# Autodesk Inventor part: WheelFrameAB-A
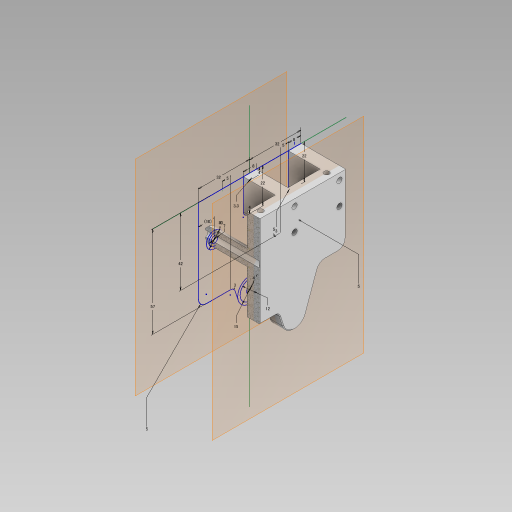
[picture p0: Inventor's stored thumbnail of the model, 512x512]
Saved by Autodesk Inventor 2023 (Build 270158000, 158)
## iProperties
Created: 2024-05
Part Number: WheelFrameAB-A
Material: 一般
Document SubType Name: Modeling
Designer: kumagai
Density: 1 g/cm^3
Appearance: 既定
Author: kumagai
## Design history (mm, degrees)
derived "WheelUnitCoreSketch.ipt"
  sketch "BaseSketch"
    geometry: L1 (0, -60.2)-(0, 60.2) reference; L2 (-60.2, 0)-(60.2, 0) reference; L3 (19, 34.059)-(19, -34.059) reference; L4 (28, 27.148)-(28, -27.148) reference; L5 (-19, 34.059)-(-19, -34.059) reference; L6 (-28, 27.148)-(-28, -27.148) reference; C1 r 43 at (0, 0) reference; 7 further points
    constraints: 1 other
  sketch "Side"
    geometry: L1 (-85.136, 0)-(85.136, 0) reference; L2 (0, 60.2)-(0, -60.2) reference; L3 (0, 22)-(-24.895, 22) reference; C1 r 10 at (-24.895, 22) reference; C2 r 34 at (-63, 0) reference; C3 r 40 at (-63, 0) reference; C4 r 2 at (-24.895, 22) reference; C5 r 17 at (-24.895, 22) reference; 2 further points
  sketch "Front"
    geometry: L1 (0, -97)-(0, -29) reference; L2 (0, -103)-(0, -23) reference; L3 (-60.2, 0)-(60.2, 0) reference; L4 (-28, 0)-(-20, 0) reference; L5 (-20, 0)-(-20, -79.404) reference; L6 (-20, -79.404)-(-28, -79.404) reference; L7 (-28, -79.404)-(-28, 0) reference; L8 (20, 0)-(28, 0) reference; L9 (28, 0)-(28, -72) reference; L10 (28, -72)-(20, -72) reference; L11 (20, -72)-(20, 0) reference; L12 (0, 0)-(0, 13.248) reference; L13 (-6, -23)-(6, -23) reference; L14 (6, -23)-(6, -103) reference; L15 (6, -103)-(-6, -103) reference; L16 (-6, -103)-(-6, -23) reference; L17 (-6.5, -29)-(-10.5, -29) reference; L18 (-10.5, -29)-(-10.5, -97) reference; L19 (-10.5, -97)-(-6.5, -97) reference; L20 (-6.5, -97)-(-6.5, -29) reference; L21 (-10.5, -34.895)-(-6.5, -34.895) reference; L22 (-6.5, -34.895)-(-6.5, -14.895) reference; L23 (-6.5, -14.895)-(-10.5, -14.895) reference; L24 (-10.5, -14.895)-(-10.5, -34.895) reference; L25 (-15.456, -24.895)-(-4.042, -24.895) reference; L26 (-18, -7.895)-(-18, -41.895) reference; L27 (-18, -7.895)-(-10.5, -14.895) reference; L28 (-10.5, -34.895)-(-18, -41.895) reference; 4 further points
sketch "スケッチ4"
  geometry: L1 (0, 60.2)-(0, -60.2) reference; L2 (-42, -19)-(-42, -27); L3 (-45.316, -14.292)-(-65.526, -7.062); L4 (-57, 27)-(-57, 12); L5 (-59.079, 9.145)-(-65.302, 7.138); L6 (0, -32)-(-37, -32); L7 (0, 32)-(-52, 32); L8 (0, 32)-(0, -32); L9 (0, 4)-(-19, 4); L10 (-22, 1)-(-22, -1); L11 (-19, -4)-(0, -4); L12 (0, -24)-(-19, -24); L13 (-22, -27)-(-22, -32); L14 (2.769, -28)-(1.321, -28); C1 r 2 at (-63, 0); C2 r 2 at (-24.895, 22); C3 r 6 at (-63, 0); C4 r 1.65 at (-4, 0); C5 r 1.65 at (-18, 0); C6 r 1.65 at (-4, -28); C7 r 1.65 at (-18, -28); C8 r 3.5 at (-24.895, 22); C9 r 5 at (-24.895, 22); A1 r 7.5 centre (-63, 0) between (-65.526, -7.062) and (-65.302, 7.138); A2 r 5 centre (-47, -19) between (-42, -19) and (-45.316, -14.292); A3 r 3 centre (-60, 12) between (-59.079, 9.145) and (-57, 12); A4 r 5 centre (-37, -27) between (-42, -27) and (-37, -32); A5 r 5 centre (-52, 27) between (-52, 32) and (-57, 27); A6 r 3 centre (-19, -27) between (-19, -24) and (-22, -27); A7 r 3 centre (-19, -1) between (-22, -1) and (-19, -4); A8 r 3 centre (-19, 1) between (-19, 4) and (-22, 1); A9 r 3 centre (-19, -29) between (-22, -29) and (-19, -32); 16 further points
  constraints: 26 end point, 18 centre point, 18 point on circle, 18 tangent, 16 point on line, 6 coincident, 6 equal radius, 2 vertical alignment, 1 parallel, 4 other
  dimensions: "d1" = 4 diameter of C1; "d2" = 4 diameter of C2; "d3" = 42 distance between parallel lines of L2 L1; "d4" = 5 vertical distance of L2.start point (0, -24); "d5" = 15 diameter of A1; "d6" = 5 radius of A2; "d7" = 57 distance between parallel lines of L4 L1; "d8" = 5 vertical distance of L4.end point (0, 17); "d9" = 3 radius of A3; "d10" = 32 distance of the line from the sketch origin of L6; "d11" = 5 radius of A4; "d13" = 12 diameter of C3; "d14" = 32 distance of the line from the sketch origin of L7; "d15" = 10 distance from line of L7 C2.centre (derived); "d16" = 5 radius of A5; "d17" = 8 distance between parallel lines of L11 L9; "d18" = 22 distance between parallel lines of L1 L10; "d19" = 8 distance between parallel lines of L6 L12; "d20" = 22 distance between parallel lines of L1 L13; "d21" = 4 distance from line of C4.centre L8; "d22" = 4 distance from line of L10 C5.centre; "d23" = 3.3 diameter of C4; "d38" = 10 diameter of C9; "d39" = 7 diameter of C8; "d70" = 3 radius of A6
node "FaceA"
node "FaceB"
extrude "SA" new body sketch "スケッチ4" stored distance "d24" = 8; taper "d25" = 0 deg
extrude "SB" join sketch "スケッチ4" stored distance "d26" = 8; taper "d27" = 0 deg
extrude "押し出し16" cut sketch "スケッチ4" stored distance "d68" = 54.8; taper "d69" = 0 deg
sketch "スケッチ5"
  geometry: C1 r 1.6 at (24, -24); C2 r 1.6 at (-24, -24); C3 r 1.6 at (24, 17); C4 r 1.6 at (-24, 17); 5 further points
  constraints: 4 centre point, 4 coincident, 3 equal radius
  dimensions: "d28" = 3.2 diameter of C1
extrude "FixHole" cut sketch "スケッチ5" extent not by distance; stored distance "d29" = 0; taper "d30" = 0 deg
extrude "WBB" join sketch "スケッチ4" stored distance "d31" = 8.9; taper "d32" = 0 deg
extrude "WBA" join sketch "スケッチ4" stored distance "d33" = 13.4; taper "d34" = 0 deg
chamfer "WBch" distance "d35" = 3; stored, may be unused: second distance "d36" = 2, angle "d37" = 45 deg
extrude "GBB" join sketch "スケッチ4" stored distance "d40" = 1.4; taper "d41" = 0 deg
extrude "GBA1" join sketch "スケッチ4" stored distance "d45" = 25.9; taper "d46" = 0 deg
extrude "GBA2" join sketch "スケッチ4" stored distance "d47" = 25.9; taper "d48" = 0 deg
chamfer "GBch1" distance "d42" = 2; stored, may be unused: second distance "d43" = 2, angle "d44" = 45 deg
extrude "STB" join sketch "スケッチ4" stored distance "d60" = 20; taper "d61" = 0 deg
extrude "STA" join sketch "スケッチ4" stored distance "d62" = 20; taper "d63" = 0 deg
chamfer "面取り4" distance "d71" = 0.5; stored, may be unused: second distance "d72" = 2, angle "d73" = 45 deg
node "ソリッド1"
